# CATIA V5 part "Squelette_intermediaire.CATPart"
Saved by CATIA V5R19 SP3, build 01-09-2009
Part number: Squelette_intermediaire
Bounding box of the stored display mesh (mm): x 0 to 0, y -20 to 77, z -76 to 76
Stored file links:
  C:\Users\Frédéric\Documents\WF\STSCPI 09-11\Projets\Projet multiplicateur eolienne\Maquette eolienne\Squelette_intermediaire.CATPart
  C:\Users\Frédéric\Documents\WF\STSCPI 09-11\Projets\Projet multiplicateur eolienne\Maquette eolienne\Multiplicateur_eolien.CATProduct
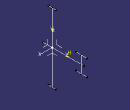
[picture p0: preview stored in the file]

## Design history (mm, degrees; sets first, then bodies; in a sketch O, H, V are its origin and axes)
External parameters (linked from other documents)
  External.Longueur = 65 mm
  `External.rayon primitif A et C` = 76 mm
  `External.rayon primitif B et D` = 18 mm
  `External.Ecartement palier arbre 39` = 90 mm
AxisSystem1: origin (0, 0, 0), X (1, 0, 0), Y (0, 1, 0), Z (0, 0, 1)
Body1 (main body)
  Sketch1 on YZ plane of AxisSystem1, origin (0, 0, 0), H (0, 1, 0), V (0, 0, 1)
    line L1 (0, 0) -> (-20, 0)
    point P1 (-20, 0)
    line L2 (0, 0) -> (65, 0)
    point P2 (65, 0)
    line L3 (65, 0) -> (70, 0)
    point P3 (70, 0)
    line L4 (65, 0) -> (65, 18)
    point P4 (65, 18)
    line L5 (65, 18) -> (53, 18)
    point P5 (53, 18)
    line L6 (65, 18) -> (77, 18)
    point P6 (77, 18)
    point P7 (65, 0)
    point P8 (65, -18)
    point P9 (53, -18)
    point P10 (77, -18)
    line L7 (65, 0) -> (65, -18)
    line L8 (65, -18) -> (53, -18)
    line L9 (65, -18) -> (77, -18)
    line L10 (0, 0) -> (0, 76)
    point P11 (0, 76)
    line L11 (0, 76) -> (-8, 76)
    point P12 (-8, 76)
    line L12 (0, 76) -> (8, 76)
    point P13 (8, 76)
    point P14 (0, 0)
    construction line L13 through (0, 0) direction (0, -1)
    point P17 (0, -76)
    point P18 (-8, -76)
    point P19 (8, -76)
    line L14 (0, 0) -> (0, -76)
    line L15 (0, -76) -> (-8, -76)
    line L16 (0, -76) -> (8, -76)
    point P20 (-20, 0)
    point P21 (70, 0)
    length L4 = 18 {= `External.rayon primitif B et D`}
    length L5 = 12
    length L6 = 12 {= Sketch1.length(L5)}
    distance L4 V = 65 {= External.Longueur}
    length L10 = 76 {= `External.rayon primitif A et C`}
    length L11 = 8
    length L12 = 8 {= Sketch1.length(L11)}
    distance V P1 = 20
    distance P1 P3 = 90 {= `External.Ecartement palier arbre 39`}
    horizontal: L1 H, L2 H, L3 H, L5 H, L6 H, L11 H, L12 H
    vertical: L4 V, L10 V
    symmetry: P2 P7 L2, P4 P8 L2, P5 P9 L2, P6 P10 L2, L4 L7 L2, L5 L8 L2, L6 L9 L2, O P14 L2, V L13 L2, P11 P17 L2, P12 P18 L2, P13 P19 L2, L10 L14 L2, L11 L15 L2, L12 L16 L2
    coincidence: P20 P1, P21 P3, O P14, P2 P7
